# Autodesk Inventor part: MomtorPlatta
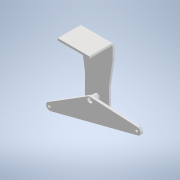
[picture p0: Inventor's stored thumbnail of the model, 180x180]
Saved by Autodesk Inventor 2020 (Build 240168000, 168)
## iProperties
Created: 2019-07
Part Number: MomtorPlatta
Material: Generic
Document SubType Name: Sheet Metal
Designer: cl
Density: 1 g/cm^3
Sheet Metal Rule: Default_mm
Appearance: Default
Author: cl
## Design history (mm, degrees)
node "Face1"
  sketch "Sketch1"
    geometry: L1 (0, 0)-(186, 0); L2 (186, 0)-(186, -80); L3 (186, -80)-(163, -235); L4 (163, -235)-(163, -410); L5 (163, -410)-(23, -410); L6 (23, -410)-(23, -235); L7 (23, -235)-(0, -80); L8 (0, -80)-(0, 0)
    constraints: 16 end point, 4 perpendicular, 1 horizontal, 1 parallel
    dimensions: "d0" = 186 distance of L1.start L1.end; "d1" = 80 distance of L1.end L2.end; "d2" = 175 distance of L3.end L4.end; "d3" = 140 distance of L4.end L5.end; "d4" = 175 distance of L5.end L6.end; "d5" = 410 distance between parallel lines of L5 L1; "d6" = 23 distance between parallel lines of L4 L2; "d7" = 80 distance of L7.end L1.start
node "Flange1"
sketch "Sketch3"
  geometry: L1 (163, -235)-(163, -410) reference; L2 (163, -410)-(23, -410) reference; C1 r 15 at (93, -318); 1 further point
  constraints: 1 centre point
  dimensions: "d19" = 30 diameter of C1; "d20" = 70 distance from line of L1 C1.centre; "d47" = 92 distance from line of L2 C1.centre
extrude "Extrusion1" join sketch "Sketch3" distance "d22" = 28; taper "d23" = 0 deg
sketch "Sketch4"
  geometry: L1 (-93, 318)-(93, 306) reference; L2 (-4.83, 18.676)-(-246.973, -132.632); L3 (-230.587, -170.772)-(284.468, -37.57); L4 (280.309, 3.732)-(-4.83, 18.676); L5 (-4.83, 18.676)-(26.941, -104.171); L6 (-404.239, 318)-(388.106, 318) reference; C1 r 15 at (0, 0) reference; A1 r 21 centre (-235.845, -150.441) between (-246.973, -132.632) and (-230.587, -170.772); A2 r 21 centre (279.21, -17.239) between (284.468, -37.57) and (280.309, 3.732)
  constraints: 8 end point, 4 point on circle, 3 tangent, 2 centre point, 1 midpoint, 1 perpendicular, 1 point on line, 2 other
  dimensions: "d48" = 21 radius of A1; "d49" = 145 deg angle of L4 L2; "d51" = 532 distance of A2.centre A1.centre; "d52" = 19.29 distance of L2.start C1.centre; "d53" = 3 deg angle of L6 L4
extrude "Extrusion2" join sketch "Sketch4" distance "d28" = 15; taper "d29" = 0 deg
sketch "Sketch5"
  geometry: C1 r 6 at (279.21, -17.239); C2 r 6 at (-235.845, -150.441); A1 r 21 centre (-235.845, -150.441) between (-246.973, -132.632) and (-230.587, -170.772) reference; A2 r 21 centre (279.21, -17.239) between (284.468, -37.57) and (280.309, 3.732) reference; 1 further point
  constraints: 2 centre point, 2 concentric
  dimensions: "d30" = 12 diameter of C1; "d31" = 12 diameter of C2
extrude "Extrusion3" join sketch "Sketch5" distance "d36" = 10; taper "d37" = 0 deg
body "Solid1"
face "Plate1" dims "d8" = 12 (= Thickness)
sketch "Sketch2"
  geometry: L1 through (93, 0) direction (-1, 0); L2 through (0, -75) direction (0, -1); L3 (0, -150)-(186, -150); L4 (186, -150)-(186, 0)
  constraints: 6 end point, 1 horizontal, 1 perpendicular, 1 vertical
face "Plate2" dims "d8" = 12 (= Thickness), "d9" = 12 (= BendReliefWidth), "d10" = 6 (= BendReliefDepth), "d11" = 24 (= MinimumRemnant), "d12" = 12 (= TransitionRadius), "d13" = 150, "d14" = -90 deg, "d15" = 12 (= BendRadius), "d16" = 48 (= CornerReliefSize), "d17" = 12 (= GapSize), "d18" = 12 (= JacobiRadiusSize), "SeamGap" = 0.01
bend "Bend1" dims "d8" = 12 (= Thickness), "d9" = 12 (= BendReliefWidth), "d10" = 6 (= BendReliefDepth), "d11" = 24 (= MinimumRemnant), "d12" = 12 (= TransitionRadius), "d13" = 150, "d14" = -90 deg, "d15" = 12 (= BendRadius), "SeamGap" = 0.01
feature "Corner1" dims "d13" = 150, "d14" = -90 deg, "d16" = 48 (= CornerReliefSize), "d17" = 12 (= GapSize), "d18" = 12 (= JacobiRadiusSize)
other parameters: "Thickness" = 12 (derived), "KFactor" = 4.4, "BendRadius" = 12 (= Thickness), "BendReliefWidth" = 12 (= Thickness), "BendReliefDepth" = 6 (= 0.5 x Thickness), "CornerReliefSize" = 48 (= 4 x Thickness), "MinimumRemnant" = 24 (= 2 x Thickness), "TransitionRadius" = 12 (= BendRadius), "JacobiRadiusSize" = 12 (= BendRadius), "GapSize" = 12 (= Thickness)
